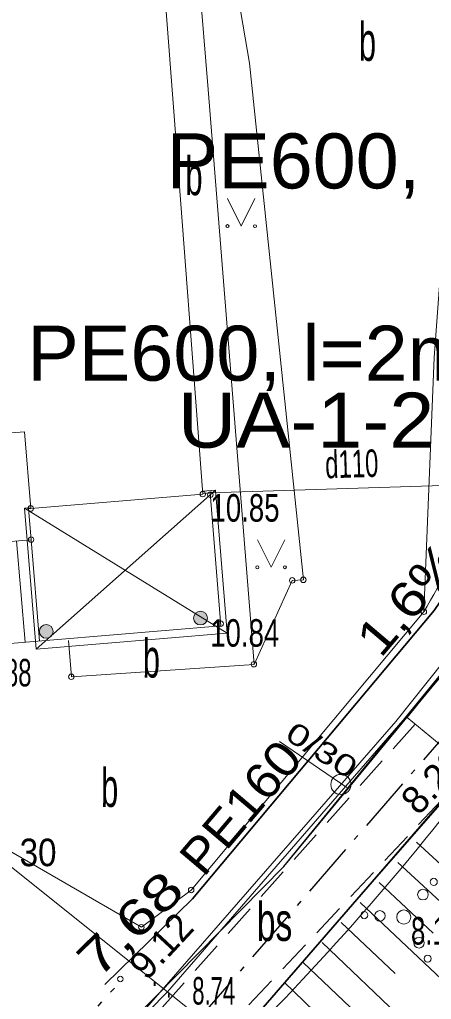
# Model space of a CAD drawing. Extents: x -1320 to -1174, y 762 to 862.
# Drawn here: x -1254.62 to -1247.14, y 811.79 to 829.59 of the extents above; entities that cross this region are included whole.
import ezdxf
from ezdxf.enums import TextEntityAlignment as Align

# ---------------------------------------------------------------- set-up
doc = ezdxf.new("R2010")
doc.units = 0
doc.header["$LTSCALE"] = 0.2
for name, pattern in [('DOT_DASHED', [7.7, 5, -1.2, 0.3, -1.2]), ('DOTTED', [1.5, 0.3, -1.2]), ('MEDIUM_DASHED', [4.5, 3, -1.5])]:
    doc.linetypes.add(name, pattern=pattern)
for name, color, linetype, lineweight in [('1', 7, 'Continuous', 13), ('11', 7, 'Continuous', 35), ('12', 7, 'Continuous', 13), ('19', 7, 'Continuous', 25), ('3', 7, 'Continuous', 13), ('30', 7, 'Continuous', 13), ('35', 7, 'Continuous', 25), ('5', 7, 'Continuous', 13), ('55', 7, 'Continuous', 13), ('56', 7, 'Continuous', 13), ('57', 7, 'DOTTED', 13), ('59', 7, 'Continuous', 13), ('6', 7, 'Continuous', 13), ('60', 7, 'Continuous', 13), ('61', 7, 'Continuous', 13), ('62', 7, 'Continuous', 13), ('63', 7, 'Continuous', 13), ('7', 7, 'Continuous', 13)]:
    doc.layers.add(name, color=color, linetype=linetype, lineweight=lineweight)
doc.layers.add('10', color=7, linetype='Continuous')
doc.layers.add('8', color=7, linetype='Continuous')

msp = doc.modelspace()

# ---------------------------------------------------------------- hatches: boundary and pattern name
at = {"layer": '7'}
for points in [[(-1251.21, 818.7142, 1), (-1251.46, 818.7142, 1)], [(-1254.01, 818.4732, 1), (-1254.26, 818.4732, 1)]]:
    msp.add_hatch(color=256, dxfattribs=at).paths.add_polyline_path(points)

# ---------------------------------------------------------------- linework, layer by layer
at = {"layer": '1'}
for p, q in [((-1248.674, 815.637), (-1249.897, 816.471)), ((-1256.057, 815.213), (-1242.15, 804.124)), ((-1247.412, 814.643), (-1246.417, 813.726)), ((-1247.751, 814.276), (-1244.455, 811.216)), ((-1248.092, 813.91), (-1247.108, 812.991)), ((-1248.434, 813.546), (-1245.172, 810.47)), ((-1248.778, 813.182), (-1247.802, 812.258)), ((-1249.122, 812.819), (-1245.881, 809.729)), ((-1249.467, 812.458), (-1248.496, 811.529)), ((-1249.813, 812.097), (-1246.578, 808.992))]:
    msp.add_line(p, q, dxfattribs=at)
msp.add_circle((-1248.7847, 815.6923), 0.1827, dxfattribs=at)
msp.add_spline([(-1235.8, 825.801), (-1237.913, 825.174), (-1239.203, 823.346), (-1241.709, 821.268), (-1246.557, 815.58), (-1256.526, 805.053), (-1260.592, 799.147), (-1261.416, 795.29), (-1262.742, 791.444), (-1262.206, 785.139)], degree=3, dxfattribs=at)
at = {"layer": '11'}
msp.add_lwpolyline([(-1253.071, 812.055), (-1251.479, 813.616), (-1247.089, 818.854), (-1245.599, 821.041)], dxfattribs=at)
at = {"layer": '19', "lineweight": 13}
msp.add_spline([(-1253.457, 785.393), (-1253.726, 794.104), (-1251.637, 801.373), (-1250.122, 804.26), (-1247.608, 807.348), (-1239.437, 815.545), (-1236.508, 819.221), (-1228.799, 821.851), (-1223.357, 826.161), (-1220.079, 827.95)], degree=3, dxfattribs=at)
at = {"layer": '3'}
msp.add_line((-1251.16, 820.99), (-1241.778, 821.284), dxfattribs=at)
at = {"layer": '30'}
msp.add_spline([(-1247.278, 818.829), (-1245.467, 822.244), (-1243.421, 828.633), (-1242.663, 831.887)], degree=3, dxfattribs=at)
at = {"layer": '35'}
msp.add_lwpolyline([(-1264.692, 791.666), (-1263.121, 794.463), (-1262.995, 800.82), (-1256.407, 807.512), (-1249.819, 814.203), (-1245.888, 819.015), (-1242.275, 823.687), (-1240.604, 825.846), (-1237.968, 829.25), (-1236.511, 829.583), (-1228.03, 831.521)], dxfattribs=at)
at = {"layer": '35', "lineweight": 35}
msp.add_lwpolyline([(-1225.362, 830.487), (-1237.056, 827.834), (-1243.981, 818.809), (-1250.833, 810.905), (-1258.147, 803.474), (-1260.339, 800.099), (-1261.472, 796.156), (-1261.529, 794.093), (-1263.29, 790.894)], dxfattribs=at)
at = {"layer": '5'}
for points in [[(-1250.845, 826.337), (-1250.595, 825.837), (-1250.345, 826.337)], [(-1250.301, 820.138), (-1250.051, 819.638), (-1249.801, 820.138)]]:
    msp.add_lwpolyline(points, dxfattribs=at)
for centre, radius in [((-1250.845, 825.8366), 0.028), ((-1250.345, 825.8366), 0.0263), ((-1250.3016, 819.6377), 0.028), ((-1249.8016, 819.6377), 0.0263), ((-1247.098, 813.9225), 0.064), ((-1247.2945, 813.6908), 0.096), ((-1248.076, 813.3039), 0.096), ((-1247.642, 813.2832), 0.128), ((-1248.3604, 813.3174), 0.064), ((-1247.3656, 812.8163), 0.096), ((-1247.2081, 812.527), 0.064)]:
    msp.add_circle(centre, radius, dxfattribs=at)
at = {"layer": '55'}
msp.add_lwpolyline([(-1279.323, 790.175), (-1264.692, 791.666), (-1263.121, 794.463), (-1263.06, 799.299), (-1247.785, 816.834), (-1237.845, 829.32), (-1225.799, 831.912), (-1223.768, 834.184)], dxfattribs=at)
at = {"layer": '56'}
for p, q in [((-1251.294, 820.98), (-1251.16, 820.99)), ((-1251.16, 820.99), (-1250.965, 818.572)), ((-1254.418, 820.706), (-1254.458, 820.703)), ((-1254.458, 820.703), (-1254.411, 820.139)), ((-1256.769, 819.942), (-1254.411, 820.139)), ((-1254.676, 820.117), (-1254.522, 818.275)), ((-1254.411, 820.139), (-1254.257, 818.297)), ((-1256.615, 818.1), (-1250.965, 818.572))]:
    msp.add_line(p, q, dxfattribs=at)
msp.add_lwpolyline([(-1247.583, 816.91), (-1246.86, 816.313), (-1245.222, 817.711), (-1244.154, 818.919), (-1245.261, 819.794)], close=True, dxfattribs=at)
at = {"layer": '57', "lineweight": 25}
msp.add_line((-1252.899, 811.989), (-1263.665, 800.388), dxfattribs=at)
at = {"layer": '59'}
for p, q in [((-1251.821, 827.921), (-1251.293, 820.967)), ((-1254.532, 822.101), (-1257.845, 821.831)), ((-1254.532, 822.101), (-1254.418, 820.706)), ((-1254.418, 820.706), (-1251.293, 820.967))]:
    msp.add_line(p, q, dxfattribs=at)
msp.add_lwpolyline([(-1251.821, 827.921), (-1252.404, 835.587), (-1252.932, 835.538), (-1252.908, 835.245), (-1258.847, 834.761), (-1258.871, 835.05), (-1260.438, 834.929)], dxfattribs=at)
at = {"layer": '6'}
for centre in [(-1251.293, 820.9672), (-1251.157, 820.9562), (-1254.418, 820.7062), (-1254.411, 820.1392), (-1249.669, 819.3992), (-1249.466, 819.4092), (-1247.278, 818.8292), (-1250.968, 818.6122), (-1250.365, 817.8762), (-1253.68, 817.6481), (-1251.504, 813.7742), (-1252.408, 813.0982), (-1252.7912, 812.1579)]:
    msp.add_circle(centre, 0.05, dxfattribs=at)
at = {"layer": '60'}
for p, q in [((-1254.318, 818.152), (-1251.065, 821.041)), ((-1251.297, 821.023), (-1251.065, 821.041)), ((-1251.065, 821.041), (-1250.848, 818.442)), ((-1254.419, 820.721), (-1254.532, 820.712)), ((-1254.532, 820.712), (-1254.318, 818.152)), ((-1254.532, 820.712), (-1250.848, 818.442)), ((-1254.318, 818.152), (-1250.848, 818.442))]:
    msp.add_line(p, q, dxfattribs=at)
at = {"layer": '61'}
for points in [[(-1249.819, 814.203), (-1246.581, 818.124), (-1237.968, 829.25), (-1225.679, 832.058)], [(-1277.32, 790.394), (-1264.695, 791.67), (-1263.123, 794.51), (-1262.995, 800.82), (-1249.819, 814.203)]]:
    msp.add_lwpolyline(points, dxfattribs=at)
at = {"layer": '62'}
msp.add_spline([(-1254.434, 786.21), (-1255.853, 794.247), (-1253.373, 799.783), (-1252.196, 801.907), (-1252.103, 801.965), (-1250.675, 804.058), (-1247.791, 807.511), (-1245.419, 810.213), (-1244.186, 811.494), (-1242.939, 812.764), (-1240.149, 815.75), (-1236.129, 820.169), (-1233.075, 822.242), (-1235.394, 825.816)], degree=3, dxfattribs=at)
at = {"layer": '63'}
for p, q in [((-1251.195, 828.321), (-1250.362, 817.869)), ((-1250.362, 817.869), (-1249.669, 819.399)), ((-1253.68, 817.648), (-1253.735, 818.308)), ((-1253.68, 817.648), (-1250.362, 817.869))]:
    msp.add_line(p, q, dxfattribs=at)
for points in [[(-1250.447, 828.8), (-1251.292, 833.762), (-1251.62, 834.676), (-1252.091, 835.555), (-1252.492, 836.196), (-1260.722, 838.754)], [(-1256.413, 835.518), (-1252.89, 835.805), (-1252.421, 835.858), (-1251.683, 834.285), (-1251.195, 828.321)], [(-1256.412, 818.123), (-1256.201, 815.29), (-1252.408, 813.098), (-1251.504, 813.774), (-1247.278, 818.829), (-1247.088, 823.447), (-1246.858, 826.564), (-1246.095, 828.381), (-1245.357, 829.125), (-1242.02, 832.546), (-1243.096, 833.394)], [(-1262.966, 796.388), (-1261.719, 800.729), (-1259.323, 804.418), (-1255.629, 808.17), (-1251.935, 811.923), (-1248.539, 815.84), (-1245.143, 819.757), (-1241.53, 824.466), (-1237.916, 829.176), (-1231.805, 830.562), (-1225.694, 831.949), (-1225.362, 830.487), (-1237.053, 827.834), (-1240.518, 823.322), (-1243.326, 819.676), (-1247.407, 814.857), (-1250.833, 810.905), (-1254.833, 806.84), (-1258.147, 803.474), (-1260.348, 800.104), (-1261.483, 796.15)], [(-1261.483, 796.15), (-1260.348, 800.104), (-1258.147, 803.474), (-1257.342, 804.291), (-1256.78, 804.862), (-1256.04, 805.612), (-1253.626, 808.067), (-1251.48, 810.249), (-1250.651, 811.111), (-1250.414, 811.388), (-1248.806, 813.242), (-1245.075, 817.511), (-1244.093, 818.684), (-1242.558, 820.667), (-1241.555, 821.963), (-1239.557, 824.569), (-1237.053, 827.834), (-1230.901, 829.229)], [(-1249.669, 819.399), (-1249.466, 819.409), (-1250.447, 828.8)]]:
    msp.add_lwpolyline(points, dxfattribs=at)
at = {"layer": '63', "linetype": 'MEDIUM_DASHED'}
for points in [[(-1265.079, 785.987), (-1263.807, 789.442), (-1261.536, 795.397), (-1260.86, 799.605), (-1256.627, 805.136), (-1246.564, 815.823), (-1241.769, 821.378), (-1239.214, 823.453), (-1237.177, 827.558), (-1234.848, 828.79), (-1231.517, 829.195), (-1224.557, 831.447)], [(-1247.437, 816.79), (-1257.209, 805.83), (-1262.318, 799.97), (-1262.654, 795.375), (-1263.503, 792.223), (-1265.015, 790.631), (-1268.643, 788.504)]]:
    msp.add_lwpolyline(points, dxfattribs=at)
at = {"layer": '63', "linetype": 'DOT_DASHED', "lineweight": 25}
msp.add_lwpolyline([(-1225.528, 831.218), (-1237.486, 828.505), (-1244.562, 819.283), (-1251.384, 811.414), (-1258.735, 803.946), (-1261.029, 800.414), (-1262.219, 796.272), (-1262.274, 794.295), (-1264.33, 790.56), (-1266.742, 787.222)], dxfattribs=at)
at = {"layer": '7'}
for centre in [(-1251.335, 818.7142), (-1254.135, 818.4732)]:
    msp.add_circle(centre, 0.125, dxfattribs=at)

# ---------------------------------------------------------------- texts
at = {"layer": '1', "width": 1.4}
msp.add_text('0/30', height=0.384, rotation=327.602, dxfattribs=at).set_placement((-1249.2339, 816.1542), align=Align.CENTER)
at = {"layer": '10'}
for s, width, p in [('b', 0.6, (-1248.302, 828.84)), ('b', 0.6, (-1251.453, 826.399)), ('b', 0.6, (-1252.227, 817.635)), ('b', 0.6, (-1252.984, 815.284)), ('bs', 0.65, (-1249.9895, 812.849))]:
    msp.add_text(s, height=0.7, dxfattribs=dict(at, width=width)).set_placement(p, align=Align.CENTER)
at = {"layer": '11', "width": 0.65}
msp.add_text('d110', height=0.5, rotation=1.795, dxfattribs=at).set_placement((-1248.5803, 821.268), align=Align.CENTER)
at = {"layer": '12', "width": 0.9}
msp.add_text('30      ', height=0.5, dxfattribs=at).set_placement((-1254.619, 814.207))
at = {"layer": '63'}
for s, width, p in [('PE600, l=2m', 1.05, (-1247.911, 826.521)), ('PE600, l=2m', 1.05, (-1250.442, 823.028)), ('UA-1-2', 1.1, (-1249.417, 821.811))]:
    msp.add_text(s, height=1, dxfattribs=dict(at, width=width)).set_placement(p, align=Align.CENTER)
for s, rotation, width, p in [('1,6%', 49.693, 1.2, (-1247.3067, 818.8625)), ('PE160', 49.693, 1.1, (-1250.3636, 815.067)), ('7,68', 44.437, 1.35, (-1252.3895, 812.9328))]:
    msp.add_text(s, height=0.64, rotation=rotation, dxfattribs=dict(at, width=width)).set_placement(p, align=Align.CENTER)
at = {"layer": '8'}
for s, width, p in [(' 10.85', 0.75, (-1251.293, 820.467)), (' 10.84', 0.75, (-1251.298, 818.195)), ('10.88', 0.65, (-1255.491, 817.473)), (' 8.15', 0.7, (-1247.642, 812.783)), ('8.74', 0.6, (-1251.485, 811.693)), ('.', 0.5, (-1252.214, 812.031)), ('.', 0.5, (-1251.957, 811.817))]:
    msp.add_text(s, height=0.5, dxfattribs=dict(at, width=width)).set_placement(p)
for s, rotation, p in [(' 8.28', 45.877, (-1247.509, 814.978)), (' 9.12', 47.084, (-1252.436, 811.977))]:
    msp.add_text(s, height=0.5, rotation=rotation, dxfattribs=at).set_placement(p)

doc.saveas('drawing.dxf')
